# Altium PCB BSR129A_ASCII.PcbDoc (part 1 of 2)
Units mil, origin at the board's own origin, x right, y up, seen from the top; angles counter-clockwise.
Board outline 2165.87 x 2165.5 mil, 2 copper layers (Top Layer, Bottom Layer), stack 61.2 mil thick; 64 components, 16 nets, 93 pads, 184 vias.
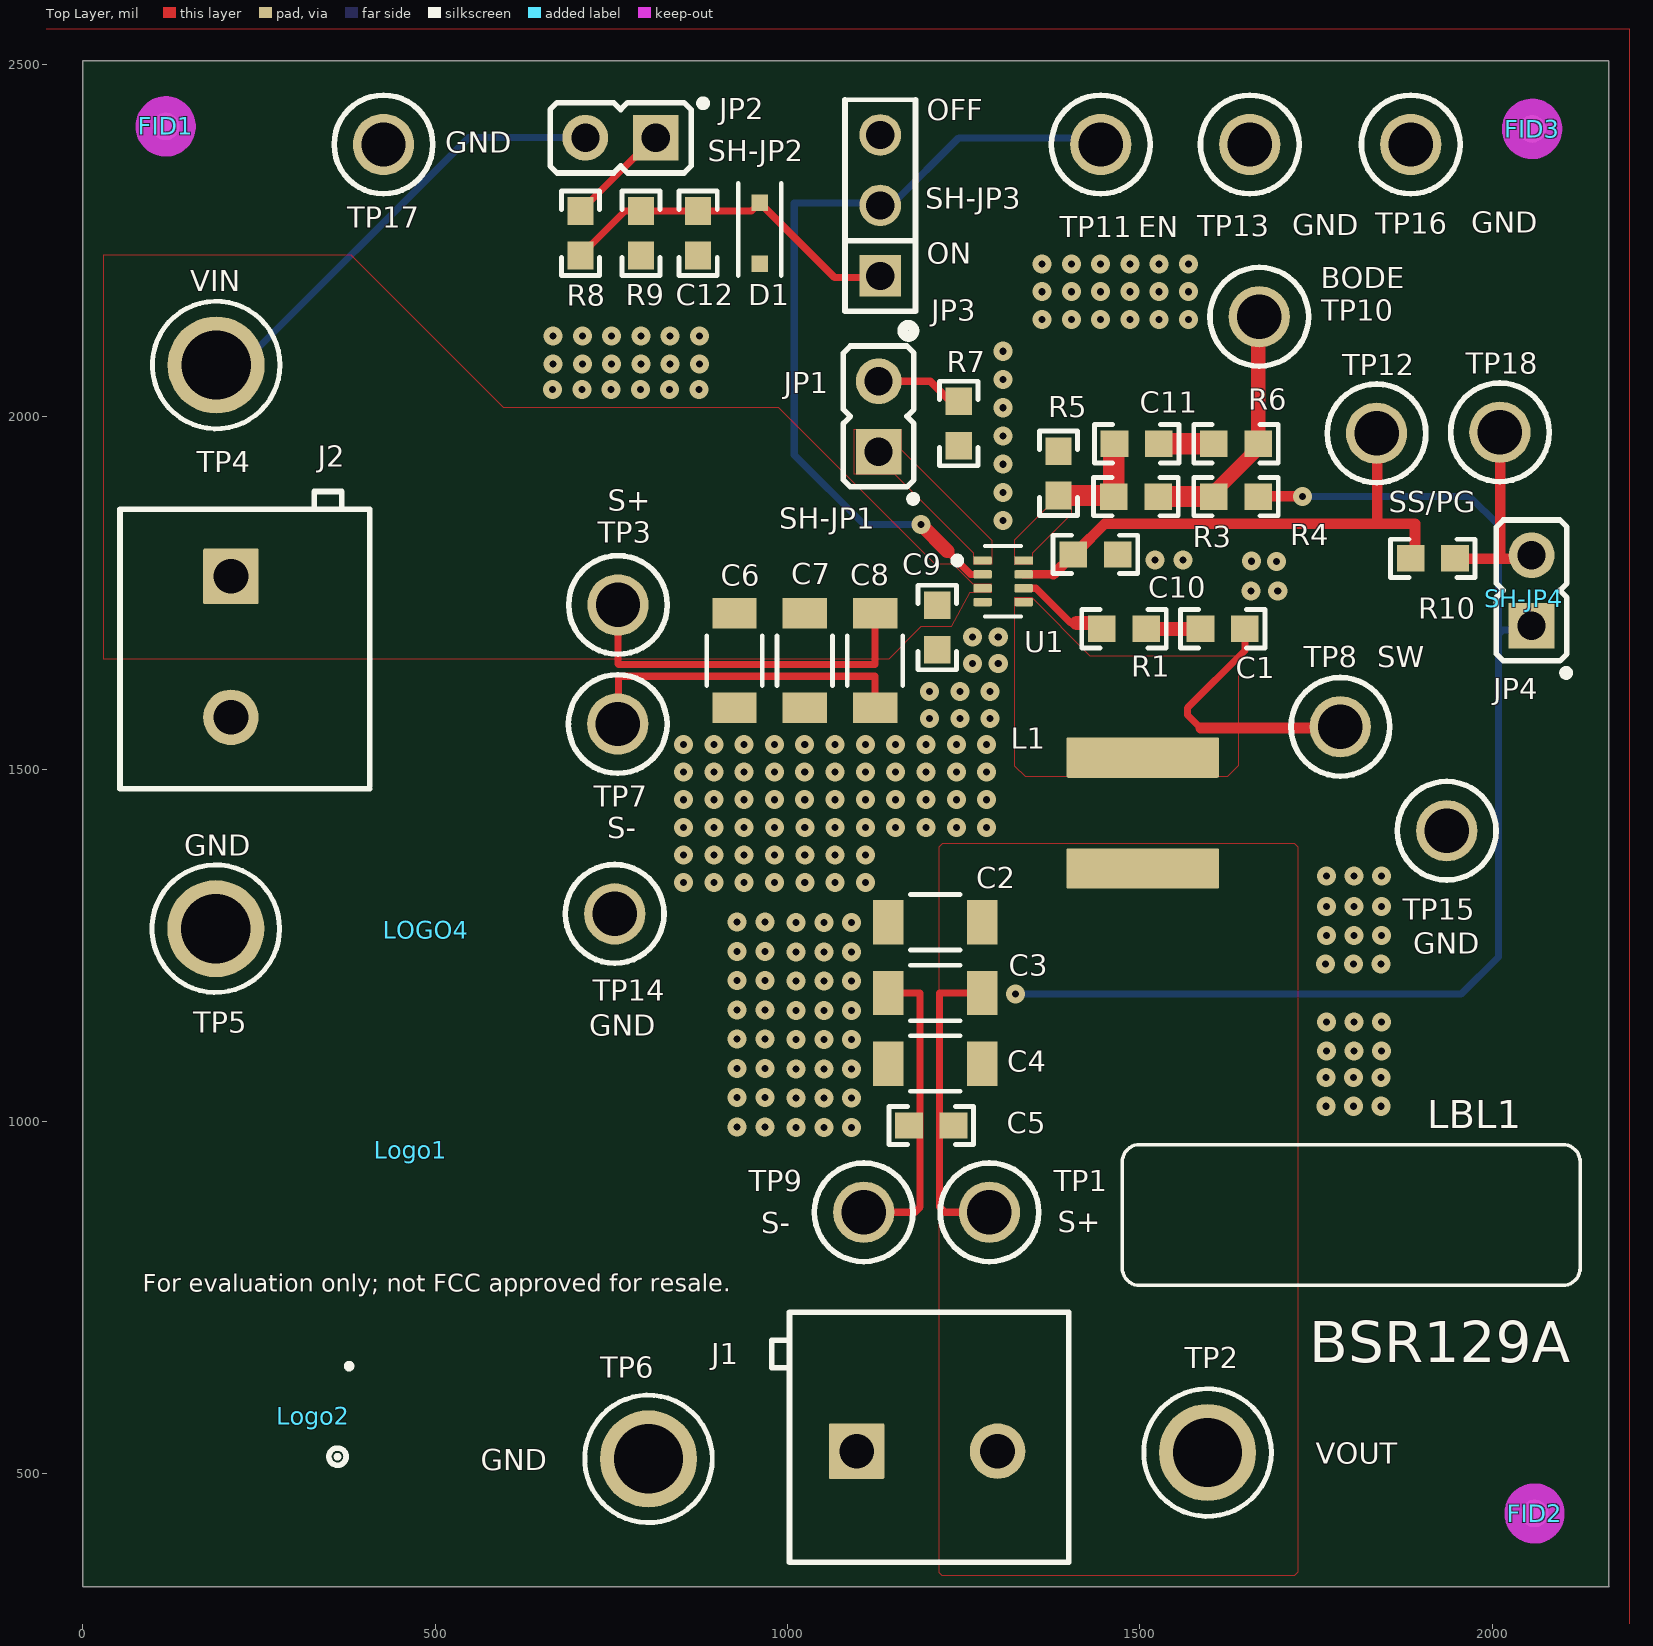
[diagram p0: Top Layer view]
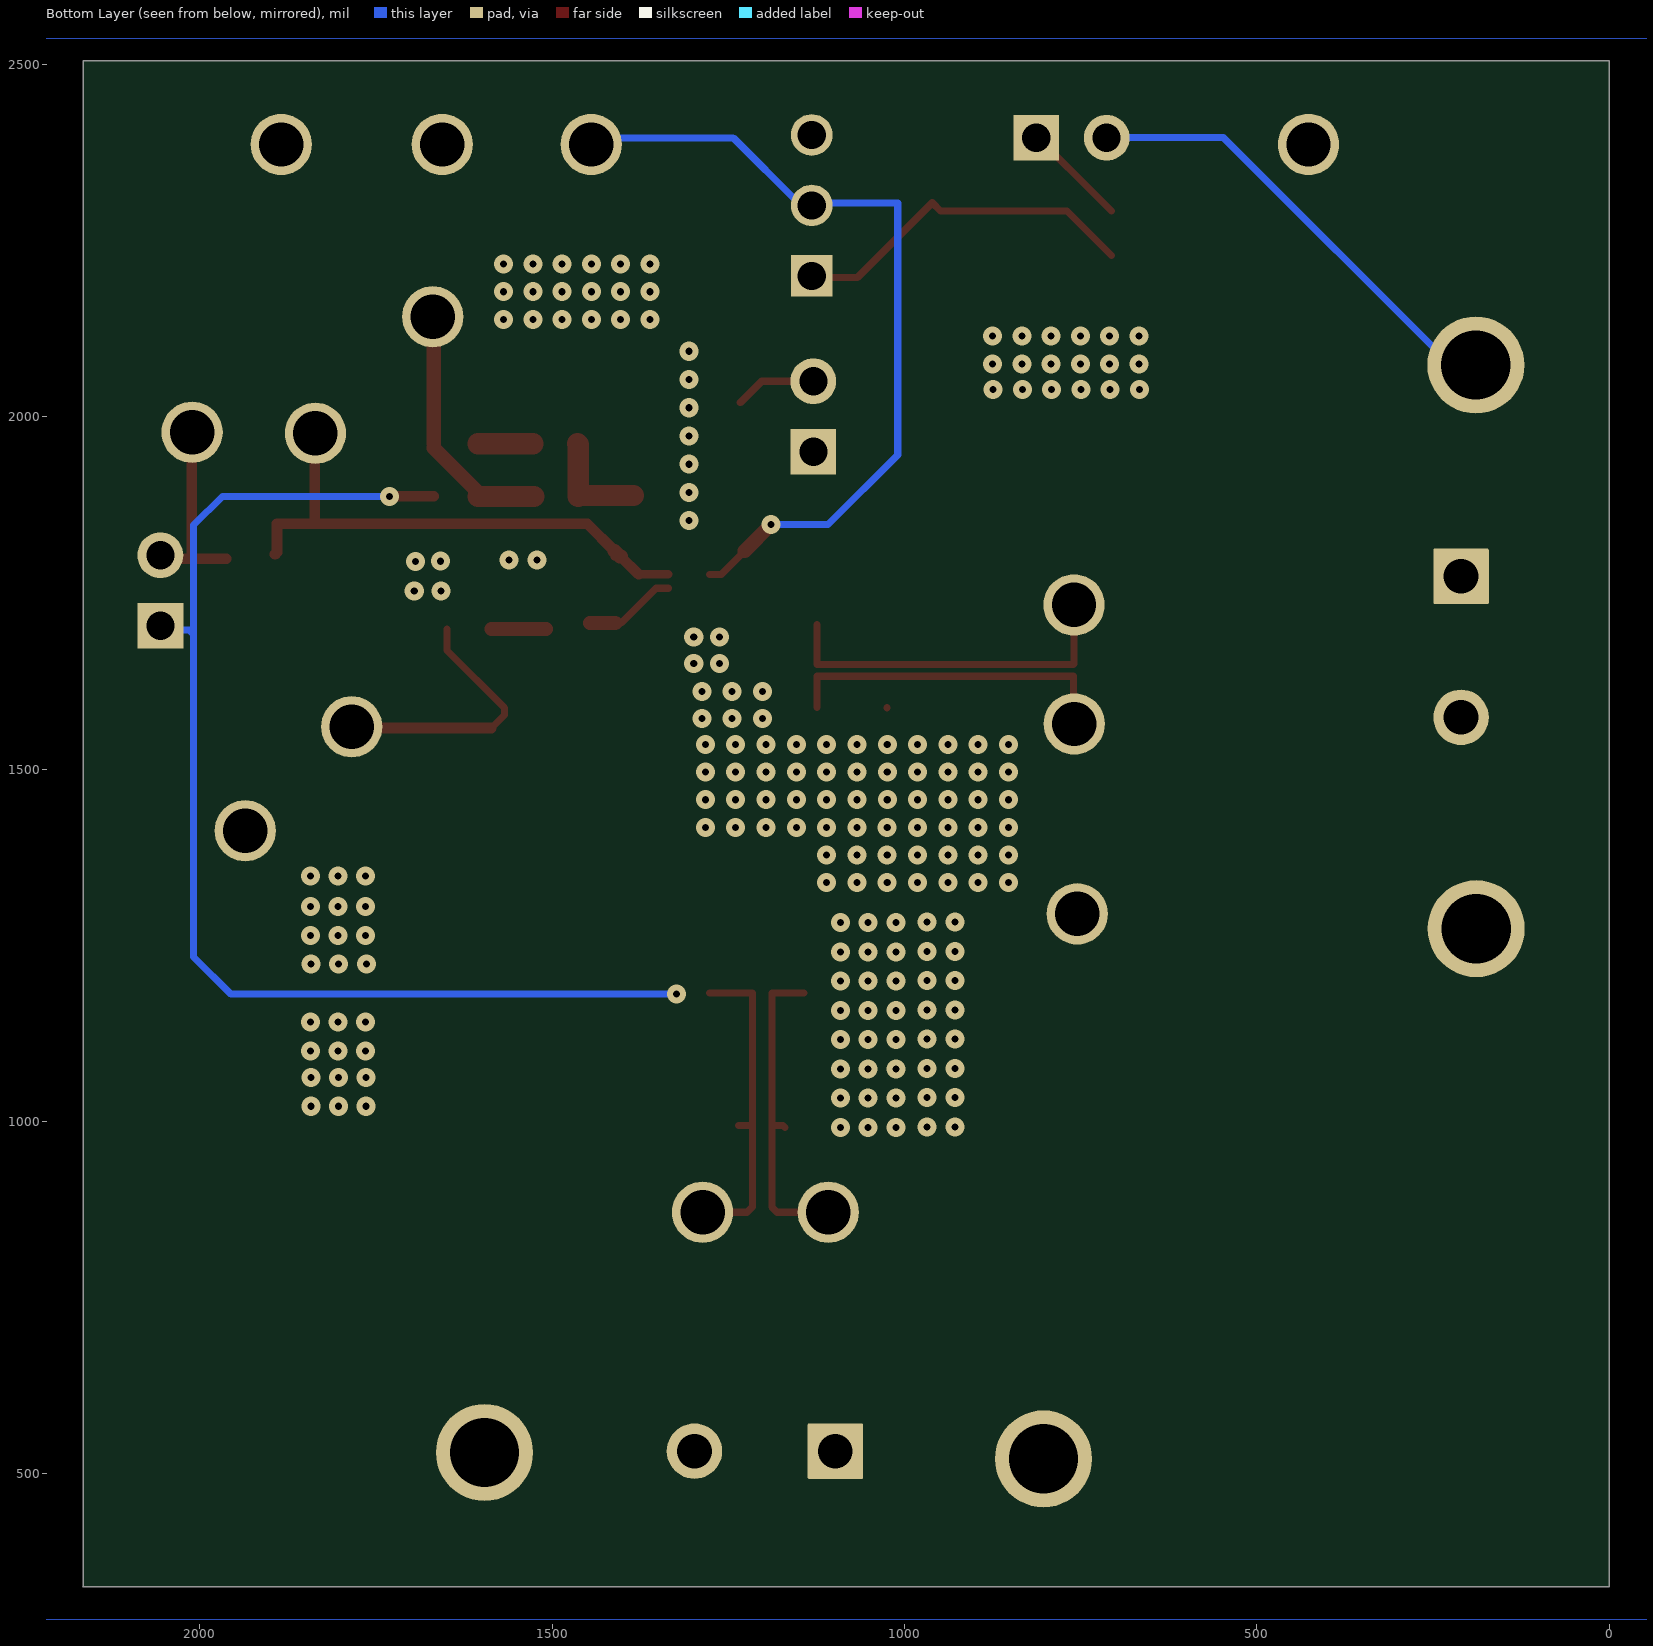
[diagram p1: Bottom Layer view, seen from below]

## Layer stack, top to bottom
Top Solder: solder mask 0.4, Solder Resist, Dk 3.5
Top Layer: signal copper 2.8
Dielectric1: core 55.6, FR-4 High Tg, Dk 4.8
Bottom Layer: signal copper 2.8
Bottom Solder: solder mask 0.4, Solder Resist, Dk 3.5

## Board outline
0,339.65 0,2505 2165.35,2505 2165.35,339.65 2165.87,339.5

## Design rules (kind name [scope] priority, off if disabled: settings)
AcuteAngle [All] p0: scope1count=1 scope1_0_kind=Board scope1_0_value=Board scope2count=1 scope2_0_kind=Board scope2_0_value=Board commentlength=0 minimum=4.50000000000000E+0001
AcuteAngle [All] p1: minimum=4.50000000000000E+0001 checktracksonly=FALSE
AssemblyTestPointUsage [All] p0: scope1count=1 scope1_0_kind=Board scope1_0_value=Board scope2count=1 scope2_0_kind=Board scope2_0_value=Board commentlength=0
AssemblyTestPointUsage [All] p1: valid=2
AssemblyTestpoint [All] p0: scope1count=1 scope1_0_kind=Board scope1_0_value=Board scope2count=1 scope2_0_kind=Board scope2_0_value=Board commentlength=0
BoardOutlineClearance BoardOutlineClearance_MountingHoles [All] p0 off: scope1count=1 scope1_0_kind=Board scope1_0_value=Board scope2count=1 scope2_0_kind=Board scope2_0_value=Board commentlength=86 gap=40 // Protel DXP Scope 1 Expression Was: OnCopper and InComponentClass('Mounting Holes')
BoardOutlineClearance BoardOutlineClearance_Poly [All] p0 off: scope1count=1 scope1_0_kind=Board scope1_0_value=Board scope2count=1 scope2_0_kind=Board scope2_0_value=Board commentlength=58 gap=25 // Protel DXP Scope 1 Expression Was: OnCopper and IsPoly
BoardOutlineClearance [All] p0 off: scope1count=1 scope1_0_kind=Board scope1_0_value=Board scope2count=1 scope2_0_kind=Board scope2_0_value=Board commentlength=172 gap=75 // Protel DXP Scope 1 Expression Was: OnCopper and Not InComponentClass('Logo') and not InComponentClass('FiducialMark') and not InRegion(1000,500,4000,800) and not InPoly
BoardOutlineClearance BoardOutlineClearance_MountingHoles [OnCopper and InComponentClass('Mounting Holes')] p1: gap=40 ignorepadtopadclearanceinfootprint=FALSE
BoardOutlineClearance BoardOutlineClearance_Poly [OnCopper and IsPoly] p2: gap=25 ignorepadtopadclearanceinfootprint=FALSE
BoardOutlineClearance [OnCopper and Not InComponentClass('Logo') and not InComponentClass('FiducialMark') and not InRegion(1000,500,4000,800) and not InPoly] p3: gap=75 ignorepadtopadclearanceinfootprint=FALSE
Clearance Clearance_Keepouts [All] p0 off: scope1count=1 scope1_0_kind=Board scope1_0_value=Board scope2count=1 scope2_0_kind=Board scope2_0_value=Board commentlength=99 gap=0 // Protel DXP Scope 2 Expression Was: ((IsTrack Or IsArc) And Not InPoly) And IsFree and IsKeepOut
Clearance Clearance_Poly [All] p0 off: scope1count=1 scope1_0_kind=Board scope1_0_value=Board scope2count=1 scope2_0_kind=Board scope2_0_value=Board commentlength=48 gap=8.5 // Protel DXP Scope 1 Expression Was: InPolygon
Clearance [All] p0: scope1count=1 scope1_0_kind=Board scope1_0_value=Board scope2count=1 scope2_0_kind=Board scope2_0_value=Board commentlength=0 gap=7
Clearance Clearance_Keepouts [((IsTrack Or IsArc) And Not InPoly) And IsFree and IsKeepOut vs ((IsTrack Or IsArc) And Not InPoly) And IsFree and IsKeepOut] p1: gap=0 ignorepadtopadclearanceinfootprint=FALSE
Clearance Clearance_Poly [InPolygon] p2: gap=8.5 ignorepadtopadclearanceinfootprint=FALSE except(0: Arc-Hole Track-Hole SMDPad-Hole THPad-Hole Via-Hole Fill-Hole Poly-Hole Region-Hole Text-Hole)
Clearance [All] p3: gap=7 ignorepadtopadclearanceinfootprint=FALSE except(0: Arc-Hole Track-Hole SMDPad-Hole THPad-Hole Via-Hole Fill-Hole Poly-Hole Region-Hole Text-Hole)
ComponentClearance ComponentClearance_MountingHoles_FiducialMarks [All] p0: scope1count=1 scope1_0_kind=ComponentClass scope1_0_value="Mounting Holes" scope2count=1 scope2_0_kind=ComponentClass scope2_0_value=FiducialMark commentlength=0 gap=50 collisioncheckmode=3
ComponentClearance ComponentClearance_Shunt [All] p0: scope1count=1 scope1_0_kind=ComponentClass scope1_0_value=Header scope2count=1 scope2_0_kind=ComponentClass scope2_0_value=Shunt commentlength=0 gap=0 collisioncheckmode=3
ComponentClearance ComponentClearance_Logo [All] p0: scope1count=1 scope1_0_kind=ComponentClass scope1_0_value=Logo scope2count=1 scope2_0_kind=Board scope2_0_value=Board commentlength=0 gap=50 collisioncheckmode=3
ComponentClearance ComponentClearance_ScrewToNut [All] p0 off: scope1count=1 scope1_0_kind=Board scope1_0_value=Board scope2count=1 scope2_0_kind=Board scope2_0_value=Board commentlength=71 gap=5 collisioncheckmode=3 // Protel DXP Scope 2 Expression Was: (HasFootprint('Keystone_1902C'))
ComponentClearance ComponentClearance_MountingHoles [All] p0: scope1count=1 scope1_0_kind=ComponentClass scope1_0_value="Mounting Holes" scope2count=1 scope2_0_kind=Board scope2_0_value=Board commentlength=0 gap=250 collisioncheckmode=3
ComponentClearance ComponentClearance_SmallPassives [All] p0 off: scope1count=1 scope1_0_kind=Board scope1_0_value=Board scope2count=1 scope2_0_kind=Board scope2_0_value=Board commentlength=508 gap=14.96 collisioncheckmode=3 // Protel DXP Scope 2 Expression Was: HasFootprint('0201*') or HasFootprint('0402*') or HasFootprint('0508') or HasFootprint('0603*') or HasFootprint('0612') or HasFootprint('0805*') or HasFootprint('0815*') or HasFootprint('0830*') or HasFootprint('1206*') or HasFootprint('1210*') or HasFootprint('1808*') or HasFootprint('1812*') or HasFootprint('1825*') or HasFootprint('2010*') or HasFootprint('2220*') or HasFootprint('2225*') or HasFootprint('2512*') or HasFootprint('2728*') or HasFootprint('3518*')
ComponentClearance ComponentClearance_THtoSMT [All] p0 off: scope1count=1 scope1_0_kind=Board scope1_0_value=Board scope2count=1 scope2_0_kind=Board scope2_0_value=Board commentlength=53 gap=40 collisioncheckmode=3 // Protel DXP Scope 2 Expression Was: IsSMTComponent
ComponentClearance ComponentClearance_THtoTH [All] p0 off: scope1count=1 scope1_0_kind=Board scope1_0_value=Board scope2count=1 scope2_0_kind=Board scope2_0_value=Board commentlength=54 gap=30 collisioncheckmode=3 // Protel DXP Scope 2 Expression Was: IsThruComponent
ComponentClearance [All] p0: scope1count=1 scope1_0_kind=Board scope1_0_value=Board scope2count=1 scope2_0_kind=Board scope2_0_value=Board commentlength=0 gap=30 collisioncheckmode=3
ComponentClearance ComponentClearance_MountingHoles_FiducialMarks [InComponentClass('Mounting Holes') vs InComponentClass('FiducialMark')] p1: gap=50 collisioncheckmode=3 verticalgap=10 showdistances=FALSE
ComponentClearance ComponentClearance_Shunt [InComponentClass('Header') vs InComponentClass('Shunt')] p2: gap=0 collisioncheckmode=3 verticalgap=0 showdistances=FALSE
ComponentClearance ComponentClearance_Logo [InComponentClass('Logo')] p3: gap=50 collisioncheckmode=3 verticalgap=10 showdistances=FALSE
ComponentClearance ComponentClearance_ScrewToNut [(HasFootprint('NY PMS 440 0025 PH')) vs (HasFootprint('Keystone_1902C'))] p4: gap=5 collisioncheckmode=3 verticalgap=10 showdistances=FALSE
ComponentClearance ComponentClearance_MountingHoles [InComponentClass('Mounting Holes')] p5: gap=250 collisioncheckmode=3 verticalgap=100000 showdistances=FALSE
ComponentClearance ComponentClearance_SmallPassives [HasFootprint('0201*') or HasFootprint('0402*') or HasFootprint('0508') or HasFootprint('0603*') or HasFootprint('0612') or HasFootprint('0805*') or HasFootprint('0815*') or HasFootprint('0830*') or HasFootprint('1206*') or HasFootprint('1210*') or HasFootprint('1808*') or HasFootprint('1812*') or HasFootprint('1825*') or HasFootprint('2010*') or HasFootprint('2220*') or HasFootprint('2225*') or HasFootprint('2512*') or HasFootprint('2728*') or HasFootprint('3518*') vs HasFootprint('0201*') or HasFootprint('0402*') or HasFootprint('0508') or HasFootprint('0603*') or HasFootprint('0612') or HasFootprint('0805*') or HasFootprint('0815*') or HasFootprint('0830*') or HasFootprint('1206*') or HasFootprint('1210*') or HasFootprint('1808*') or HasFootprint('1812*') or HasFootprint('1825*') or HasFootprint('2010*') or HasFootprint('2220*') or HasFootprint('2225*') or HasFootprint('2512*') or HasFootprint('2728*') or HasFootprint('3518*')] p6: gap=14.96 collisioncheckmode=3 verticalgap=10 showdistances=FALSE
ComponentClearance ComponentClearance_THtoSMT [IsThruComponent vs IsSMTComponent] p7: gap=40 collisioncheckmode=3 verticalgap=30 showdistances=FALSE
ComponentClearance ComponentClearance_THtoTH [IsThruComponent vs IsThruComponent] p8: gap=30 collisioncheckmode=3 verticalgap=30 showdistances=FALSE
ComponentClearance [All] p9: gap=30 collisioncheckmode=3 verticalgap=10 showdistances=FALSE
DiffPairsRouting [All] p0: scope1count=1 scope1_0_kind=Board scope1_0_value=Board scope2count=1 scope2_0_kind=Board scope2_0_value=Board commentlength=0
DiffPairsRouting [All] p1: maxlimit=100 minlimit=10 mostfreqgap=10 toplayer_minwidth=15 toplayer_maxwidth=15 toplayer_prefwidth=15 bottomlayer_minwidth=15 bottomlayer_maxwidth=15 bottomlayer_prefwidth=15 maxuncoupledlength=1000
FabricationTestPointUsage TestPointUsage [All] p0: scope1count=1 scope1_0_kind=Board scope1_0_value=Board scope2count=1 scope2_0_kind=Board scope2_0_value=Board commentlength=0 valid=2 allowmultiple=FALSE
FabricationTestPointUsage TestPointUsage [All] p1: valid=2 allowmultiple=FALSE
FabricationTestpoint Testpoint [All] p0: scope1count=1 scope1_0_kind=Board scope1_0_value=Board scope2count=1 scope2_0_kind=Board scope2_0_value=Board commentlength=0 side=3 testpointundercomponent=TRUE minsize=40 maxsize=100 preferedsize=60 minholesize=0 maxholesize=40 preferedholesize=32 testpointgrid=1
FabricationTestpoint Testpoint [All] p1: side=3 testpointundercomponent=TRUE minsize=40 maxsize=100 preferedsize=60 minholesize=0 maxholesize=40 preferedholesize=32 testpointgrid=1 allowsidetop=TRUE allowsidebottom=TRUE usegrid=TRUE gridtolerance=0.01
FanoutControl Fanout_LCC [All] p0 off: scope1count=1 scope1_0_kind=Board scope1_0_value=Board scope2count=1 scope2_0_kind=Board scope2_0_value=Board commentlength=69 // Protel DXP Scope 1 Expression Was: IsLCC   Fanout_LCC (Default Rule)
FanoutControl Fanout_BGA [All] p0 off: scope1count=1 scope1_0_kind=Board scope1_0_value=Board scope2count=1 scope2_0_kind=Board scope2_0_value=Board commentlength=69 // Protel DXP Scope 1 Expression Was: IsBGA   Fanout_BGA (Default Rule)
FanoutControl Fanout_SOIC [All] p0 off: scope1count=1 scope1_0_kind=Board scope1_0_value=Board scope2count=1 scope2_0_kind=Board scope2_0_value=Board commentlength=71 // Protel DXP Scope 1 Expression Was: IsSOIC   Fanout_SOIC (Default Rule)
FanoutControl Fanout_Default [All] p0: scope1count=1 scope1_0_kind=Board scope1_0_value=Board scope2count=1 scope2_0_kind=Board scope2_0_value=Board commentlength=30 // Fanout_Default (Default Rule)
FanoutControl Fanout_Small [All] p0 off: scope1count=1 scope1_0_kind=Board scope1_0_value=Board scope2count=1 scope2_0_kind=Board scope2_0_value=Board commentlength=84 // Protel DXP Scope 1 Expression Was: (CompPinCount < 5)   Fanout_Small (Default Rule)
FanoutControl Fanout_LCC [IsLCC] p1: bgadir=Out bgaviamode=Centered fanoutstyle=Auto fanoutdirection=Alternating viagrid=1 // Fanout_LCC (Default Rule)
FanoutControl Fanout_BGA [IsBGA] p2: bgadir=Out bgaviamode=Centered fanoutstyle=Auto fanoutdirection=Alternating viagrid=1 // Fanout_BGA (Default Rule)
FanoutControl Fanout_Default [All] p4: bgadir=Out bgaviamode=Centered fanoutstyle=Auto fanoutdirection=Alternating viagrid=1 // Fanout_Default (Default Rule)
FanoutControl Fanout_Small [(CompPinCount < 5)] p5: bgadir=Out bgaviamode=Centered fanoutstyle=Auto fanoutdirection=OutThenIn viagrid=1 // Fanout_Small (Default Rule)
Height [All] p0: scope1count=1 scope1_0_kind=Board scope1_0_value=Board scope2count=1 scope2_0_kind=Board scope2_0_value=Board commentlength=0
HoleSize [All] p0: scope1count=1 scope1_0_kind=Board scope1_0_value=Board scope2count=1 scope2_0_kind=Board scope2_0_value=Board commentlength=0 absolutevalues=TRUE maxlimit=251 minlimit=7.87 maxpercent=80.000 minpercent=20.000
HoleSize [All] p1: absolutevalues=TRUE maxlimit=251 minlimit=7.87 maxpercent=80.000 minpercent=20.000
HoleToHoleClearance [All] p0: scope1count=1 scope1_0_kind=Board scope1_0_value=Board scope2count=1 scope2_0_kind=Board scope2_0_value=Board commentlength=0
LayerPairs [All] p0: scope1count=1 scope1_0_kind=Board scope1_0_value=Board scope2count=1 scope2_0_kind=Board scope2_0_value=Board commentlength=0 enforce=TRUE
MinimumAnnularRing MinimumAnnularRing_ThermalPadVias [All] p0 off: scope1count=1 scope1_0_kind=Board scope1_0_value=Board scope2count=1 scope2_0_kind=Board scope2_0_value=Board commentlength=63 minimumring=5.91 // Protel DXP Scope 1 Expression Was: IsVia and InAnyComponent
MinimumAnnularRing [All] p0: scope1count=1 scope1_0_kind=Board scope1_0_value=Board scope2count=1 scope2_0_kind=Board scope2_0_value=Board commentlength=0 minimumring=6
MinimumAnnularRing MinimumAnnularRing_ThermalPadVias [IsVia and InAnyComponent] p1: minimumring=5.91
MinimumAnnularRing [All] p2: minimumring=6
MinimumSolderMaskSliver MinimumSolderMaskSliver_Logo [All] p0: scope1count=1 scope1_0_kind=ComponentClass scope1_0_value=Logo scope2count=1 scope2_0_kind=ComponentClass scope2_0_value=Logo commentlength=0
MinimumSolderMaskSliver [All] p0: scope1count=1 scope1_0_kind=Board scope1_0_value=Board scope2count=1 scope2_0_kind=Board scope2_0_value=Board commentlength=0
MinimumSolderMaskSliver MinimumSolderMaskSliver_Logo [InComponentClass('Logo') vs InComponentClass('Logo')] p1: minsoldermaskwidth=0.7
MinimumSolderMaskSliver [All] p2: minsoldermaskwidth=3.94
NetAntennae [All] p0: scope1count=1 scope1_0_kind=Board scope1_0_value=Board scope2count=1 scope2_0_kind=Board scope2_0_value=Board commentlength=0
PasteMaskExpansion [All] p0: scope1count=1 scope1_0_kind=Board scope1_0_value=Board scope2count=1 scope2_0_kind=Board scope2_0_value=Board commentlength=0 expansion=0
PlaneClearance [All] p0: scope1count=1 scope1_0_kind=Board scope1_0_value=Board scope2count=1 scope2_0_kind=Board scope2_0_value=Board commentlength=0 clearance=0
PlaneClearance [All] p1: clearance=0
PlaneConnect [All] p0: scope1count=1 scope1_0_kind=Board scope1_0_value=Board scope2count=1 scope2_0_kind=Board scope2_0_value=Board commentlength=0 planeconnectstyle=Direct reliefexpansion=10 reliefentries=2 reliefconductorwidth=10 reliefairgap=10
PlaneConnect [All] p1: planeconnectstyle=Direct reliefexpansion=10 reliefentries=2 reliefconductorwidth=10 reliefairgap=10
PolygonConnect [All] p0: scope1count=1 scope1_0_kind=Board scope1_0_value=Board scope2count=1 scope2_0_kind=Board scope2_0_value=Board commentlength=0 connectstyle=Direct reliefconductorwidth=10 reliefentries=4 polygonreliefangle="90 Angle"
PolygonConnect [All] p1: connectstyle=Direct reliefconductorwidth=10 reliefentries=4 polygonreliefangle="90 Angle" airgapwidth=10
RoutingCorners [All] p0: scope1count=1 scope1_0_kind=Board scope1_0_value=Board scope2count=1 scope2_0_kind=Board scope2_0_value=Board commentlength=0 cornerstyle=45-Degree minsetback=100 maxsetback=100
RoutingLayers [All] p0: scope1count=1 scope1_0_kind=Board scope1_0_value=Board scope2count=1 scope2_0_kind=Board scope2_0_value=Board commentlength=0 top layer=Automatic bottom layer=Automatic
RoutingPriority [All] p0: scope1count=1 scope1_0_kind=Board scope1_0_value=Board scope2count=1 scope2_0_kind=Board scope2_0_value=Board commentlength=0
RoutingTopology [All] p0: scope1count=1 scope1_0_kind=Board scope1_0_value=Board scope2count=1 scope2_0_kind=Board scope2_0_value=Board commentlength=0 topology=Shortest
RoutingVias ThermalPadVias [All] p0 off: scope1count=1 scope1_0_kind=Board scope1_0_value=Board scope2count=1 scope2_0_kind=Board scope2_0_value=Board commentlength=63 holewidth=7.87 width=19.68 viastyle="Through Hole" minholewidth=7.87 minwidth=19.68 maxholewidth=12.99 maxwidth=23.62 // Protel DXP Scope 1 Expression Was: IsVia and InAnyComponent
RoutingVias [All] p0: scope1count=1 scope1_0_kind=Board scope1_0_value=Board scope2count=1 scope2_0_kind=Board scope2_0_value=Board commentlength=0 holewidth=16 width=34 viastyle="Through Hole" minholewidth=7.87 minwidth=26 maxholewidth=40 maxwidth=65
RoutingVias ThermalPadVias [IsVia and InAnyComponent] p1: holewidth=7.87 width=19.68 viastyle="Through Hole" minholewidth=7.87 minwidth=19.68 maxholewidth=12.99 maxwidth=23.62
RoutingVias [All] p2: holewidth=16 width=34 viastyle="Through Hole" minholewidth=7.87 minwidth=26 maxholewidth=40 maxwidth=65
ShortCircuit [All] p0: scope1count=1 scope1_0_kind=Board scope1_0_value=Board scope2count=1 scope2_0_kind=Board scope2_0_value=Board commentlength=0 allowed=FALSE
SilkToBoardRegionClearance [All] p0 off: scope1count=1 scope1_0_kind=Board scope1_0_value=Board scope2count=1 scope2_0_kind=Board scope2_0_value=Board commentlength=130 // Protel DXP Scope 1 Expression Was: Not ((IsComment or IsDesignator) And (Hide <> 'False')) and not InRegion(1000,500,4000,800)
SilkToBoardRegionClearance [Not ((IsComment or IsDesignator) And (Hide <> 'False')) and not InRegion(1000,500,4000,800)] p1:
SilkToSilkClearance SilkToSilkClearance_Pb-FreeLogo [All] p0 off: scope1count=1 scope1_0_kind=Board scope1_0_value=Board scope2count=1 scope2_0_kind=Board scope2_0_value=Board commentlength=120 // Protel DXP Scope 2 Expression Was: (HasFootprint('Pb-Free_Overlay_Medium') OR HasFootprint('Pb-Free_Overlay_Small'))
SilkToSilkClearance [All] p0: scope1count=1 scope1_0_kind=Board scope1_0_value=Board scope2count=1 scope2_0_kind=Board scope2_0_value=Board commentlength=0
SilkToSilkClearance SilkToSilkClearance_Pb-FreeLogo [(HasFootprint('Pb-Free_Overlay_Medium') OR HasFootprint('Pb-Free_Overlay_Small')) vs (HasFootprint('Pb-Free_Overlay_Medium') OR HasFootprint('Pb-Free_Overlay_Small'))] p1: silktosilkclearance=0
SilkToSilkClearance [All] p2: silktosilkclearance=4
SilkToSolderMaskClearance SilkToComponentPadClearance [All] p0 off: scope1count=1 scope1_0_kind=Board scope1_0_value=Board scope2count=1 scope2_0_kind=Board scope2_0_value=Board commentlength=87 // Protel DXP Scope 1 Expression Was: (IsPad or IsFill or IsRegion) and InAnycomponent
SilkToSolderMaskClearance "Silk to Solder Mask Opening" [All] p0: scope1count=1 scope1_0_kind=Board scope1_0_value=Board scope2count=1 scope2_0_kind=Board scope2_0_value=Board commentlength=0
SilkToSolderMaskClearance SilkToComponentPadClearance [(IsPad or IsFill or IsRegion) and InAnycomponent] p1: minsilkscreentomaskgap=2 clearancetoexposedcopper=TRUE
SilkToSolderMaskClearance "Silk to Solder Mask Opening" [All] p2: minsilkscreentomaskgap=0.5 clearancetoexposedcopper=TRUE
SolderMaskExpansion [All] p0: scope1count=1 scope1_0_kind=Board scope1_0_value=Board scope2count=1 scope2_0_kind=Board scope2_0_value=Board commentlength=0 expansion=1.85
SolderMaskExpansion [All] p1: expansion=1.85
UnRoutedNet [All] p0: scope1count=1 scope1_0_kind=Board scope1_0_value=Board scope2count=1 scope2_0_kind=Board scope2_0_value=Board commentlength=0
UnpouredPolygon [All] p0: scope1count=1 scope1_0_kind=Board scope1_0_value=Board scope2count=1 scope2_0_kind=Board scope2_0_value=Board commentlength=0
Width [All] p0: scope1count=1 scope1_0_kind=Board scope1_0_value=Board scope2count=1 scope2_0_kind=Board scope2_0_value=Board commentlength=0 maxlimit=100 minlimit=3 preferedwidth=10
Width [All] p1: maxlimit=100 minlimit=3 preferedwidth=10 bottomlayer_minwidth=6 minimp=50.000000 maximp=50.000000 favimp=50.000000 checkconnectedcopper=TRUE
14 further rules are at their usual default settings.

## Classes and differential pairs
component class Label: LBL1
component class Shunt: SH-JP1 SH-JP2 SH-JP3 SH-JP4
component class FiducialMark: FID1 FID2 FID3
component class BSR129A_Hardware: FID1 FID2 FID3 LBL1 Logo1 Logo2 Logo3 LOGO4 LOGO7 SH-JP1 SH-JP2 SH-JP3 SH-JP4 ZZ1 ZZ2 ZZ3 ZZ4
component class Logo: Logo1
component class Header: JP1 JP2 JP3 JP4
component class BSR129A: 2 C1 C2 C3 C4 C5 C6 C7 C8 C9 C11 C12 D1 GND GND3 J1 J2 JP1 JP2 JP3 JP4 L1 R1 R3 R4 R5 R6 R7 R8 R9 R10 TP1 TP2 TP3 TP4 TP5 TP6 TP7 TP8 TP9 TP10 TP11 TP12 TP13 TP14 TP15 TP16 TP17 TP18 U1 VIN1 VOUT0
component class AssemblyNote: ZZ1 ZZ2 ZZ3 ZZ4

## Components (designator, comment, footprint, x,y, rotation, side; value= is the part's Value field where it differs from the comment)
C1 "C0603C104K5RACAUTO" 0603 1617.5,1699 r180 top
C2 "C3216X5R1V226M160AC" 1206_180 1209.5,1282.5 r180 top
C3 "C3216X5R1V226M160AC" 1206_180 1209.5,1182.25 r180 top
C4 "C3216X5R1V226M160AC" 1206_180 1209.5,1082 r180 top
C5 "C0603C104K5RACAUTO" 0603 1204,994.16 r180 top
C6 "CGA5L1X7R1H106K160AC" 1206_190 924.75,1653.97 r270 top
C7 "CGA5L1X7R1H106K160AC" 1206_190 1024.5,1653.97 r270 top
C8 "CGA5L1X7R1H106K160AC" 1206_190 1124.25,1653.97 r270 top
C9 "C0603C104K5RACAUTO" 0603 1212.5,1700.98 r270 top
C10 "06035C333JAT2A" 0603 1437,1804.65 r0 top
C11 "C0603C100J5GACTU" 0603 1495.47,1961.73 r180 top
C12 "C0603C103J5RACTU" 0603 872.9,2260.45 r270 top
D1 "Zener" SOD-323 960.5,2260.51 r270 top
FID1 "Fiducial" Fiducial10-20 117.37,2412.09 r0 top
FID2 "Fiducial" Fiducial10-20 2060.13,443.5 r0 top
FID3 "Fiducial" Fiducial10-20 2056.63,2408.59 r0 top
J1 "ED120/2DS" On-Shore_ED120_2DS 1198,532 r0 top
J2 "ED120/2DS" On-Shore_ED120_2DS 210,1673.5 r270 top
JP1 "PBC02SAAN" Sullins_PBC02SAAN 1129.27,2000.48 r180 top
JP2 "PBC02SAAN" Sullins_PBC02SAAN 763,2396 r270 top
JP3 "PEC03SAAN" CONN_PEC03SAAN 1131.5,2300 r90 top
JP4 "PBC02SAAN" Sullins_PBC02SAAN 2056,1753.5 r180 top
L1 "74439346068" WE-XHMI_6060 1504,1437.5 r270 top
LBL1 "THT-14-423-10" Label_650x200 1800,867.16 r0 top
Logo1 "Texas Instruments" TI_Stacked_Overlay_Small 465,959 r0 top
Logo2 "WEEE logo" WEEE_Minimum 327.15,582.5 r0 top
Logo3 "FCC disclaimer" FCC_disclaimer 5235,-1337.5 r90 top
LOGO4 "CE Mark" CE_Mark_5mm 487,1272 r0 top
R1 "RC0603JR-070RL" 0603 1477.5,1699 r0 top
R3 "RC0603FR-0749R9L" 0603 1636.47,1886.73 r0 top
R4 "RC0603FR-0753K6L" 0603 1494.48,1886.73 r0 top
R5 "RC0603FR-0710K2L" 0603 1384.48,1919.73 r270 top
R6 "RC0603JR-070RL" 0603 1636.48,1961.73 r0 top
R7 "RC0603JR-070RL" 0603 1243,1990.5 r90 top
R8 "RC0603FR-0749K9L" 0603 706.17,2260.45 r90 top
R9 "RC0603FR-0749K9L" 0603 792,2260.45 r90 top
R10 "RC0603FR-07100KL" 0603 1915.82,1799 r180 top
SH-JP1 "SNT-100-BK-G" SNT-100-BK-G 1079.27,1941.5 r0 top
SH-JP2 "SNT-100-BK-G" SNT-100-BK-G 765.59,2393 r0 top
SH-JP3 "SNT-100-BK-G" SNT-100-BK-G 1131,2247 r270 top
SH-JP4 "SNT-100-BK-G" SNT-100-BK-G 2045.5,1742.71 r90 top
TP1 "VOUT" Keystone5010 1286.5,871 r0 top
TP2 "1502-2" Keystone1502-2 1596,530 r0 top
TP3 "VIN" Keystone5010 759.33,1733 r0 top
TP4 "1502-2" Keystone1502-2 189,2073.5 r0 top
TP5 "1502-2" Keystone1502-2 188.5,1273.5 r0 top
TP6 "1502-2" Keystone1502-2 802.6,521 r0 top
TP7 "GND" Keystone5011 759,1564 r0 top
TP8 "SW" Keystone5014 1784.55,1560 r0 top
TP9 "GND" Keystone5011 1108,871 r0 top
TP10 "Bode" Keystone5014 1669.5,2142 r0 top
TP11 "EN" Keystone5014 1444.5,2386.5 r0 top
TP12 "SS" Keystone5014 1836,1976.5 r0 top
TP13 "GND" Keystone5011 1656,2386.5 r0 top
TP14 "GND" Keystone5011 754.65,1294.5 r0 top
TP15 "GND" Keystone5011 1935.5,1412.5 r0 top
TP16 "GND" Keystone5011 1884.5,2386.5 r0 top
TP17 "GND" Keystone5011 426.5,2386.5 r0 top
TP18 "PG" Keystone5014 2011,1978 r0 top
U1 "TPS62933DRLR" DRL0008A-MFG 1305.87,1766.53 r0 top
ZZ1 "This Assembly Note is for PCB labels only" AssemblyNoteLabel 3685.5,756.5 r0 top
ZZ2 "These assemblies are ESD sensitive, ESD precautions shall be observed." AssemblyNote 3687.5,612 r0 top
ZZ3 "These assemblies must be clean and free from flux and all contaminants. Use of no clean flux is not acceptable." AssemblyNote 3687.5,488.5 r0 top
ZZ4 "These assemblies must comply with workmanship standards IPC-A-610 Class 2., unless otherwise specified." AssemblyNote 3687.5,356 r0 top

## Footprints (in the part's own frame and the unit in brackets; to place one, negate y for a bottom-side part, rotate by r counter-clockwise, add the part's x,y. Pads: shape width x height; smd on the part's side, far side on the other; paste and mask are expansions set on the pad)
0603 [mm] "0603 from SM-752 data"
  rect 1x0.95 smd: 1(-0.8,0) 2(0.8,0)
  silkscreen extent -1.52,-0.69 1.52,0.69
1206_180 [mm] "1206_180"
  rect 1.1x1.6 smd: 1(-1.7,0) 2(1.7,0)
  silkscreen extent -0.9,-1 0.9,1
1206_190 [mm] "1206_190"
  rect 1.1x1.6 smd: 1(-1.7,0) 2(1.7,0)
  silkscreen extent -0.9,-1 0.9,1
AssemblyNote [mil] "Assembly Note"
AssemblyNoteLabel [mil] "Assembly Note for PCB Labels"
CE_Mark_5mm [mil] "Minimum text height for CE Mark"
CONN_PEC03SAAN [mm] "SULLINS"
  rect 1.5x1.5 hole 1.016: 1(-2.54,0)
  round 1.5 hole 1.016: 2(0,0) 3(2.54,0)
  silkscreen extent -4.72,-1.27 3.81,1.27
DRL0008A-MFG [mm]
  rrect33% 0.67x0.3 smd paste+0 mask+0: 1(-0.74,0.75) 2(-0.74,0.25) 3(-0.74,-0.25) 4(-0.74,-0.75) 5(0.74,-0.75) 6(0.74,-0.25) 7(0.74,0.25) 8(0.74,0.75)
  silkscreen extent -1.77,-1.28 0.65,1.28
FCC_disclaimer [mil]
Fiducial10-20 [mm]
  round 1 smd mask+0: 1(0,0)
  Top Layer keep-out circle w1.178: c0,0 r0.5
Keystone1502-2 [mm] "Double Turret"
  round 3.5 hole 2.5: 1(0,0)
  silkscreen extent -2.3,-2.3 2.3,2.3
Keystone5010 [mil] "Keystone Multipurpose loops"
  round 87 hole 63: 1(0,0)
  silkscreen extent -70,-70 70,70
Keystone5011 [mil] "Keystone Multipurpose loops"
  round 87 hole 63: 1(0,0)
  silkscreen extent -70,-70 70,70
Keystone5014 [mil] "Keystone Multipurpose loops"
  round 87 hole 63: 1(0,0)
  silkscreen extent -70,-70 70,70
Label_650x200 [mil] "Thermal Transfer Label"
  round 1 on Mech13: 0(0,0)
  silkscreen extent -325,-100 325,100
On-Shore_ED120_2DS [mm] "ONSHORE"
  rrect5% 2x2 hole 1.25: 1(-2.54,0)
  round 2 hole 1.25: 2(2.54,0)
  silkscreen extent -5.6,-4 5.12,5
SNT-100-BK-G [mil] "Samtec STEP model"
  round 1 on Mech3: 0(0,0)
SOD-323 [mm] "NXP recommended land pattern"
  rect 0.6x0.6 smd paste-0.05: 1(-1.1,0) 2(1.1,0)
  silkscreen extent -1.8,-0.77 1.53,0.77
Sullins_PBC02SAAN [mm] "Sullins 100mil, 1x2, 230 mil above insulator"
  rect 1.65x1.65 hole 1.016: 1(0,1.27)
  round 1.65 hole 1.016: 2(0,-1.27)
  silkscreen extent -1.37,-2.54 1.27,3.1
TI_Stacked_Overlay_Small [mil]
WE-XHMI_6060 [mm] "SMD, 2-Leads, Body 6.65x6.45mm"
  rrect7% 1.45x5.5 smd: 1(-2,0) 2(2,0)
WEEE_Minimum [mil] "WEEElie bin"
  silkscreen extent 22,-71 54,74

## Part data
C1 C5 C9: library part CMP-0079602-1, "CAP, CERM, 0.1 µF, 50 V,+/- 10%, X7R, AEC-Q200 Grade 1, 0603"
C2 C3 C4: library part CMP-0008667-2, "CAP, CERM, 22 uF, 35 V, +/- 20%, X5R, 1206"
C6 C7 C8: library part CMP-0085950-1, "CAP, CERM, 10 µF, 50 V,+/- 10%, X7R, AEC-Q200 Grade 1, 1206"
C10: library part CMP-0006806-1, "CAP, CERM, 0.033 uF, 50 V, +/- 5%, X7R, 0603"
C11: library part CMP-0006839-4, "CAP, CERM, 10 pF, 50 V, +/- 5%, C0G/NP0, 0603"
C12: library part CMP-0006850-4, "CAP, CERM, 0.01 uF, 50 V, +/- 5%, X7R, 0603"
D1: library part CMP-0005854-3, "Diode, Zener, 5.1 V, 200 mW, SOD-323"
FID1 FID2 FID3: library part CMP-0077181-1, "Fiducial mark.  There is nothing to buy or mount."
J1 J2: library part CMP-0074910-1, "Terminal Block, 5.08 mm, 2x1, Brass, TH"
JP1 JP2 JP4: library part CMP-0054566-1, "Header, 100mil, 2x1, Gold, TH"
JP3: library part CMP-0002338-1, "Header, 100mil, 3x1, Tin, TH"
L1: library part CMP-0085369-1, "Inductor, Shielded, Hyperflux, 6.8 µH, 6.5 A, 0.01936 ohm, SMD"
LBL1: library part CMP-0003625-1, "Thermal Transfer Printable Labels, 0.650\" W x 0.200\" H - 10,000 per roll"
Logo1: library part CMP-0074838-1, "Texas Instrument Corporate Signature"
Logo2: library part CMP-0074769-1
Logo3: library part CMP-0074847-1, "FCC_disclaimer"
LOGO4: library part CMP-0074844-1
R1 R6 R7: library part CMP-0025885-5, "RES, 0, 5%, 0.1 W, 0603"
R3: library part CMP-0023143-5, "RES, 49.9, 1%, 0.1 W, 0603"
R4: library part CMP-0023176-5, "RES, 53.6 k, 1%, 0.1 W, 0603"
R5: library part CMP-0022743-5, "RES, 10.2 k, 1%, 0.1 W, 0603"
R8 R9: library part CMP-0023142-5, "RES, 49.9 k, 1%, 0.1 W, 0603"
R10: library part CMP-0022735-5, "RES, 100 k, 1%, 0.1 W, 0603"
SH-JP1 SH-JP2 SH-JP3 SH-JP4: library part CMP-0003623-3, "Shunt, 100mil, Gold plated, Black"
TP1 TP3: library part CMP-0055147-1, "Test Point, Multipurpose, Red, TH"
TP2 TP4 TP5 TP6: library part CMP-0055113-1, "Terminal, Turret, TH, Double"
TP7 TP9 TP13 TP14 TP15 TP16 TP17: library part CMP-0055148-1, "Test Point, Multipurpose, Black, TH"
TP8 TP10 TP11 TP12 TP18: library part CMP-0055151-1, "Test Point, Multipurpose, Yellow, TH"
U1: library part CMP-0090998-1, "3.8-V to 30-V Input, 3-A/2-A, 300kHz-2.2MHz, Low IQ Synchronous Buck Converter in SOT583 Package"
ZZ1: library part CMP-0003616-3
ZZ2: library part CMP-0077236-1
ZZ3: library part CMP-0077237-1
ZZ4: library part AssemblyNote

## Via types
v1: diameter 27, hole 10, Top Layer to Bottom Layer, 184 vias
